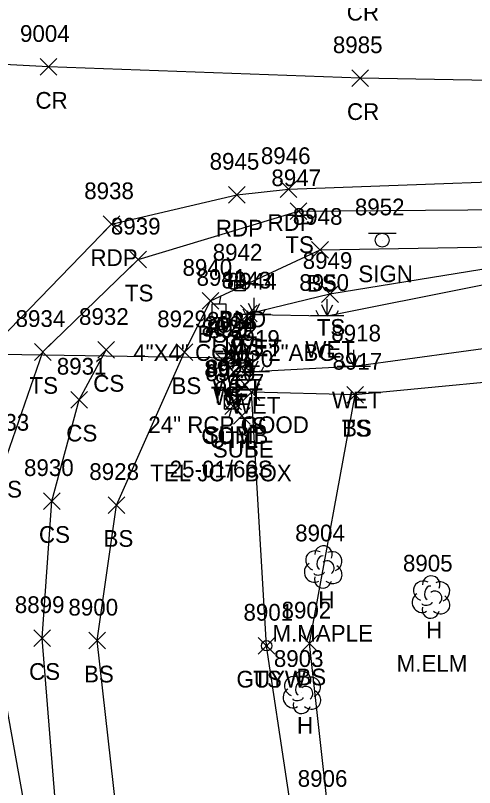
# Model space of a CAD drawing. Extents: x 1462089 to 1464015, y 730534 to 736144.
# Drawn here: x 1463265.1 to 1463320, y 734884.2 to 734976.7 of the extents above; entities that cross this region are included whole.
import ezdxf

# ---------------------------------------------------------------- set-up
doc = ezdxf.new("R2010")
doc.units = 0
for name, color, linetype in [('D_A', 7, 'Continuous'), ('D_C', 7, 'Continuous'), ('D_I', 7, 'Continuous'), ('D_TIC', 7, 'Continuous'), ('DCP', 7, 'Continuous'), ('L_A', 7, 'Continuous'), ('L_C', 7, 'Continuous'), ('L_I', 7, 'Continuous'), ('L_TIC', 7, 'Continuous'), ('LELB', 7, 'Continuous'), ('LTD', 7, 'Continuous'), ('LWET', 7, 'Continuous'), ('M_A', 7, 'Continuous'), ('M_C', 7, 'Continuous'), ('M_I', 7, 'Continuous'), ('MHBP', 7, 'Continuous'), ('P_A', 7, 'Continuous'), ('P_I', 7, 'Continuous'), ('P_TIC', 7, 'Continuous'), ('PET', 7, 'Continuous'), ('PRC', 7, 'Continuous'), ('S_A', 7, 'Continuous'), ('S_I', 7, 'Continuous'), ('SSGN', 7, 'Continuous'), ('U_A', 7, 'Continuous'), ('U_C', 7, 'Continuous'), ('U_I', 7, 'Continuous'), ('U_TIC', 7, 'Continuous'), ('UDEFAULT', 7, 'Continuous'), ('ULP', 7, 'Continuous'), ('UP', 7, 'Continuous'), ('UPGW', 7, 'Continuous')]:
    doc.layers.add(name, color=color, linetype=linetype)

msp = doc.modelspace()

# ---------------------------------------------------------------- linework, layer by layer
at = {"layer": 'D_TIC'}
for points in [[(1463290.042, 734934.667), (1463292.042, 734936.667)], [(1463292.042, 734934.667), (1463290.042, 734936.667)]]:
    msp.add_lwpolyline(points, dxfattribs=at)
at = {"layer": 'DCP'}
msp.add_lwpolyline([(1463180.1, 734937.44), (1463291.042, 734935.667)], dxfattribs=at)
at = {"layer": 'L_TIC'}
for points in [[(1463297.971, 734952.221), (1463299.971, 734954.221)], [(1463299.971, 734952.221), (1463297.971, 734954.221)], [(1463300.533, 734947.593), (1463302.533, 734949.593)], [(1463302.533, 734947.593), (1463300.533, 734949.593)], [(1463278.758, 734946.428), (1463280.758, 734948.428)], [(1463280.758, 734946.428), (1463278.758, 734948.428)], [(1463301.727, 734942.315), (1463303.727, 734944.315)], [(1463303.727, 734942.315), (1463301.727, 734944.315)], [(1463287.412, 734941.494), (1463289.412, 734943.494)], [(1463289.412, 734941.494), (1463287.412, 734943.494)], [(1463292.007, 734939.973), (1463294.007, 734941.973)], [(1463294.007, 734939.973), (1463292.007, 734941.973)], [(1463267.338, 734935.371), (1463269.338, 734937.371)], [(1463269.338, 734935.371), (1463267.338, 734937.371)], [(1463274.938, 734935.616), (1463276.938, 734937.616)], [(1463276.938, 734935.616), (1463274.938, 734937.616)], [(1463284.305, 734935.334), (1463286.305, 734937.334)], [(1463286.305, 734935.334), (1463284.305, 734937.334)], [(1463289.045, 734934.223), (1463291.045, 734936.223)], [(1463291.045, 734934.223), (1463289.045, 734936.223)], [(1463292.334, 734930.57), (1463294.334, 734932.57)], [(1463294.334, 734930.57), (1463292.334, 734932.57)], [(1463292.334, 734930.57), (1463294.334, 734932.57)], [(1463294.334, 734930.57), (1463292.334, 734932.57)], [(1463271.708, 734929.66), (1463273.708, 734931.66)], [(1463273.708, 734929.66), (1463271.708, 734931.66)], [(1463304.73, 734930.253), (1463306.73, 734932.253)], [(1463306.73, 734930.253), (1463304.73, 734932.253)], [(1463304.73, 734930.253), (1463306.73, 734932.253)], [(1463306.73, 734930.253), (1463304.73, 734932.253)], [(1463268.436, 734917.529), (1463270.436, 734919.529)], [(1463270.436, 734917.529), (1463268.436, 734919.529)], [(1463276.169, 734917.054), (1463278.169, 734919.054)], [(1463278.169, 734917.054), (1463276.169, 734919.054)], [(1463267.254, 734901.129), (1463269.254, 734903.129)], [(1463269.254, 734901.129), (1463267.254, 734903.129)], [(1463273.832, 734900.825), (1463275.832, 734902.825)], [(1463275.832, 734900.825), (1463273.832, 734902.825)], [(1463294.137, 734900.213), (1463296.137, 734902.213)], [(1463296.137, 734900.213), (1463294.137, 734902.213)], [(1463299.265, 734900.473), (1463301.265, 734902.473)], [(1463301.265, 734900.473), (1463299.265, 734902.473)]]:
    msp.add_lwpolyline(points, dxfattribs=at)
at = {"layer": 'LELB'}
for points in [[(1463264.438, 734721.407), (1463263.507, 734771.236), (1463263.833, 734824.888), (1463270.027, 734860.541), (1463262.385, 734902.806), (1463264.021, 734923.95), (1463268.338, 734936.371), (1463279.758, 734947.428), (1463298.971, 734953.221), (1463339.528, 734953.531), (1463370.453, 734953.761)], [(1463274.437, 734722.017), (1463275.239, 734770.638), (1463277.634, 734823.964), (1463279.43, 734861.116), (1463274.832, 734901.825), (1463277.169, 734918.054), (1463285.305, 734936.334), (1463288.412, 734942.494), (1463301.533, 734948.593), (1463339.117, 734949.223), (1463370.465, 734949.424)], [(1463341.575, 734817.643), (1463321.491, 734824.397), (1463302.22, 734837.233), (1463300.766, 734858.163), (1463300.153, 734867.868), (1463295.137, 734901.213), (1463293.334, 734931.57), (1463290.045, 734935.223), (1463293.007, 734940.973), (1463302.727, 734943.315), (1463339.117, 734949.223)], [(1463359.784, 734936.972), (1463331.585, 734933.717), (1463305.73, 734931.253), (1463293.334, 734931.57)], [(1463268.889, 734721.541), (1463269.274, 734771.054), (1463270.408, 734824.446), (1463271.473, 734862.411), (1463268.254, 734902.129), (1463269.436, 734918.529), (1463272.708, 734930.66), (1463275.938, 734936.616)], [(1463343.192, 734822.583), (1463325.193, 734831.999), (1463308.067, 734843.504), (1463305.277, 734856.307), (1463304.048, 734867.373), (1463300.265, 734901.473), (1463305.73, 734931.253)]]:
    msp.add_lwpolyline(points, dxfattribs=at)
at = {"layer": 'LTD'}
for p, q in [((1463301.894, 734910.707), (1463301.894, 734910.707)), ((1463301.894, 734910.707), (1463301.894, 734910.707)), ((1463314.798, 734907.093), (1463314.798, 734907.093)), ((1463314.798, 734907.093), (1463314.798, 734907.093)), ((1463299.344, 734895.677), (1463299.344, 734895.677)), ((1463299.344, 734895.677), (1463299.344, 734895.677))]:
    msp.add_line(p, q, dxfattribs=at)
for centre in [(1463301.941, 734912.141), (1463314.845, 734908.527), (1463299.391, 734897.111)]:
    msp.add_arc(centre, 1.047, 335.52715, 180.95627, dxfattribs=at)
for centre, major_axis, ratio, start_param, end_param in [((1463301.102, 734911.373), (1.21, -0.512), 0.895232, 1.570796, 4.712389), ((1463301.686, 734911.165), (-0.208, -0.792), 0.645439, 3.141593, 6.283185), ((1463302.936, 734911.29), (-1.141, -0.483), 0.949671, 1.570796, 4.712389), ((1463300.811, 734909.998), (0.584, -1.042), 0.959034, 3.141593, 6.283185), ((1463302.394, 734910.54), (-0.5, 0.667), 0.989748, 3.141593, 6.283185), ((1463302.894, 734909.873), (-1.09, 0.792), 0.841452, 1.570796, 4.712389), ((1463301.894, 734909.207), (0.265, 1.061), 0.942809, 1.570796, 4.712389), ((1463301.436, 734909.956), (-0.625, -0.083), 0.423636, 0, 3.141593), ((1463314.006, 734907.759), (1.21, -0.512), 0.895232, 1.570796, 4.712389), ((1463314.59, 734907.551), (-0.208, -0.792), 0.645439, 3.141593, 6.283185), ((1463315.84, 734907.676), (-1.141, -0.483), 0.949671, 1.570796, 4.712389), ((1463313.715, 734906.384), (0.584, -1.042), 0.959034, 3.141593, 6.283185), ((1463315.298, 734906.926), (-0.5, 0.667), 0.989748, 3.141593, 6.283185), ((1463314.34, 734906.343), (-0.625, -0.083), 0.423636, 0, 3.141593), ((1463315.798, 734906.26), (-1.09, 0.792), 0.841452, 1.570796, 4.712389), ((1463314.798, 734905.593), (0.265, 1.061), 0.942809, 1.570796, 4.712389), ((1463298.552, 734896.344), (1.21, -0.512), 0.895232, 1.570796, 4.712389), ((1463300.385, 734896.261), (-1.141, -0.483), 0.949671, 1.570796, 4.712389), ((1463299.135, 734896.136), (-0.208, -0.792), 0.645439, 3.141593, 6.283185), ((1463299.844, 734895.511), (-0.5, 0.667), 0.989748, 3.141593, 6.283185), ((1463298.261, 734894.969), (0.584, -1.042), 0.959034, 3.141593, 6.283185), ((1463300.344, 734894.844), (-1.09, 0.792), 0.841452, 1.570796, 4.712389), ((1463299.344, 734894.177), (0.265, 1.061), 0.942809, 1.570796, 4.712389), ((1463298.886, 734894.927), (-0.625, -0.083), 0.423636, 0, 3.141593)]:
    msp.add_ellipse(centre, major_axis=major_axis, ratio=ratio, start_param=start_param, end_param=end_param, dxfattribs=at)
at = {"layer": 'LWET'}
for p, q in [((1463293.653, 734940.839), (1463293.653, 734942.839)), ((1463302.401, 734940.682), (1463302.401, 734942.682)), ((1463293.653, 734940.839), (1463292.986, 734942.172)), ((1463293.653, 734940.839), (1463294.32, 734942.172)), ((1463302.401, 734940.682), (1463301.734, 734942.015)), ((1463302.401, 734940.682), (1463303.067, 734942.015)), ((1463295.653, 734940.839), (1463291.653, 734940.839)), ((1463292.653, 734940.839), (1463292.32, 734941.505)), ((1463294.653, 734940.839), (1463294.986, 734941.505)), ((1463304.401, 734940.682), (1463300.401, 734940.682)), ((1463301.401, 734940.682), (1463301.067, 734941.349)), ((1463303.401, 734940.682), (1463303.734, 734941.349)), ((1463291.266, 734936.156), (1463291.266, 734938.156)), ((1463291.266, 734936.156), (1463290.6, 734937.489)), ((1463291.266, 734936.156), (1463291.933, 734937.489)), ((1463291.38, 734935.016), (1463291.38, 734937.016)), ((1463293.266, 734936.156), (1463289.266, 734936.156)), ((1463290.266, 734936.156), (1463289.933, 734936.823)), ((1463291.38, 734935.016), (1463290.713, 734936.349)), ((1463291.38, 734935.016), (1463292.047, 734936.349)), ((1463292.266, 734936.156), (1463292.6, 734936.823)), ((1463293.47, 734933.987), (1463293.47, 734935.987)), ((1463305.577, 734934.638), (1463305.577, 734936.638)), ((1463290.38, 734935.016), (1463290.047, 734935.683)), ((1463292.38, 734935.016), (1463292.713, 734935.683)), ((1463293.47, 734933.987), (1463292.803, 734935.32)), ((1463293.47, 734933.987), (1463294.136, 734935.32)), ((1463304.577, 734934.638), (1463304.244, 734935.305)), ((1463305.577, 734934.638), (1463304.91, 734935.972)), ((1463305.577, 734934.638), (1463306.244, 734935.972)), ((1463306.577, 734934.638), (1463306.91, 734935.305)), ((1463293.38, 734935.016), (1463289.38, 734935.016)), ((1463292.47, 734933.987), (1463292.136, 734934.653)), ((1463294.47, 734933.987), (1463294.803, 734934.653)), ((1463307.577, 734934.638), (1463303.577, 734934.638)), ((1463295.47, 734933.987), (1463291.47, 734933.987))]:
    msp.add_line(p, q, dxfattribs=at)
msp.add_lwpolyline([(1463359.703, 734939.534), (1463331.295, 734938.128), (1463305.577, 734934.638), (1463293.47, 734933.987), (1463291.38, 734935.016), (1463291.266, 734936.156), (1463293.653, 734940.839), (1463302.401, 734940.682), (1463338.181, 734947.84), (1463369.972, 734946.235)], dxfattribs=at)
at = {"layer": 'MHBP'}
msp.add_lwpolyline([(1463291.32, 734944.929), (1463292.57, 734944.929), (1463292.57, 734943.679), (1463291.32, 734943.679)], close=True, dxfattribs=at)
msp.add_circle((1463291.945, 734944.304), 0.0833, dxfattribs=at)
at = {"layer": 'P_TIC'}
for points in [[(1463268.026, 734969.49), (1463270.026, 734971.49)], [(1463270.026, 734969.49), (1463268.026, 734971.49)], [(1463305.329, 734968.142), (1463307.329, 734970.142)], [(1463307.329, 734968.142), (1463305.329, 734970.142)], [(1463296.764, 734954.867), (1463298.764, 734956.867)], [(1463298.764, 734954.867), (1463296.764, 734956.867)], [(1463290.574, 734954.193), (1463292.574, 734956.193)], [(1463292.574, 734954.193), (1463290.574, 734956.193)], [(1463275.556, 734950.663), (1463277.556, 734952.663)], [(1463277.556, 734950.663), (1463275.556, 734952.663)]]:
    msp.add_lwpolyline(points, dxfattribs=at)
at = {"layer": 'PET'}
msp.add_lwpolyline([(1463257.855, 734929.751), (1463261.821, 734936.51), (1463276.556, 734951.663), (1463291.574, 734955.193), (1463297.764, 734955.867), (1463339.315, 734957.368), (1463370.338, 734956.311)], dxfattribs=at)
at = {"layer": 'PRC'}
msp.add_lwpolyline([(1463370.424, 734967.11), (1463339.737, 734968.555), (1463306.329, 734969.142), (1463269.026, 734970.49), (1463257.64, 734971.099)], dxfattribs=at)
at = {"layer": 'SSGN'}
for p, q in [((1463307.335, 734950.582), (1463310.668, 734950.582)), ((1463308.982, 734949.748), (1463308.982, 734949.748))]:
    msp.add_line(p, q, dxfattribs=at)
msp.add_circle((1463308.982, 734949.748), 0.833, dxfattribs=at)
at = {"layer": 'U_TIC'}
for points in [[(1463290.126, 734929.462), (1463292.126, 734931.462)], [(1463292.126, 734929.462), (1463290.126, 734931.462)], [(1463291.169, 734927.74), (1463293.169, 734929.74)], [(1463293.169, 734927.74), (1463291.169, 734929.74)]]:
    msp.add_lwpolyline(points, dxfattribs=at)
at = {"layer": 'UDEFAULT'}
for points in [[(1463290.138, 734928.89), (1463292.138, 734930.89)], [(1463292.138, 734928.89), (1463290.138, 734930.89)]]:
    msp.add_lwpolyline(points, dxfattribs=at)
at = {"layer": 'ULP'}
for p, q in [((1463289.608, 734942.963), (1463289.442, 734942.129)), ((1463288.608, 734940.463), (1463288.608, 734942.129)), ((1463288.608, 734942.129), (1463290.275, 734942.129)), ((1463290.275, 734942.129), (1463290.275, 734940.463)), ((1463289.442, 734941.296), (1463289.442, 734941.296)), ((1463290.275, 734940.463), (1463288.608, 734940.463)), ((1463289.192, 734939.629), (1463289.442, 734940.463))]:
    msp.add_line(p, q, dxfattribs=at)
at = {"layer": 'UP'}
for p, q in [((1463291.182, 734932.033), (1463290.932, 734931.2)), ((1463290.098, 734929.533), (1463290.098, 734931.2)), ((1463290.098, 734931.2), (1463291.765, 734931.2)), ((1463291.765, 734931.2), (1463291.765, 734929.533)), ((1463291.765, 734929.533), (1463290.098, 734929.533)), ((1463290.682, 734928.7), (1463290.932, 734929.533)), ((1463290.932, 734930.367), (1463290.932, 734930.367))]:
    msp.add_line(p, q, dxfattribs=at)
msp.add_circle((1463290.932, 734930.367), 0.833, dxfattribs=at)
at = {"layer": 'UPGW'}
for radius in [0.625, 0.0833]:
    msp.add_circle((1463295.137, 734901.213), radius, dxfattribs=at)

# ---------------------------------------------------------------- texts
at = {"layer": 'D_A'}
msp.add_text('P', height=2, dxfattribs=at).set_placement((1463290.42, 734930.667))
at = {"layer": 'D_C'}
msp.add_text('24" RCP GOOD', height=2, dxfattribs=at).set_placement((1463280.971, 734926.667))
at = {"layer": 'D_I'}
msp.add_text('2094', height=2, dxfattribs=at).set_placement((1463287.703, 734938.667))
at = {"layer": 'L_A'}
for s, p in [('TS', (1463297.38, 734948.221)), ('BS', (1463299.974, 734943.593)), ('TS', (1463278.167, 734942.428)), ('TS', (1463301.137, 734938.315)), ('BS', (1463286.853, 734937.494)), ('WET', (1463291.031, 734935.839)), ('TS', (1463291.417, 734935.973)), ('WET', (1463299.779, 734935.682)), ('TS', (1463266.747, 734931.371)), ('CS', (1463274.378, 734931.616)), ('BS', (1463283.746, 734931.334)), ('WET', (1463288.644, 734931.156)), ('TS', (1463288.455, 734930.223)), ('WET', (1463288.758, 734930.016)), ('WET', (1463302.955, 734929.638)), ('WET', (1463290.848, 734928.987)), ('TS', (1463291.744, 734926.57)), ('TS', (1463291.744, 734926.57)), ('CS', (1463271.149, 734925.66)), ('TS', (1463304.14, 734926.253)), ('BS', (1463304.171, 734926.253)), ('TS', (1463262.43, 734918.95)), ('CS', (1463267.877, 734913.529)), ('BS', (1463275.61, 734913.054)), ('H', (1463301.327, 734905.707)), ('H', (1463314.231, 734902.093)), ('CS', (1463266.695, 734897.129)), ('BS', (1463273.273, 734896.825)), ('TS', (1463293.547, 734896.213)), ('BS', (1463298.706, 734896.473)), ('H', (1463298.777, 734890.677))]:
    msp.add_text(s, height=2, dxfattribs=at).set_placement(p)
at = {"layer": 'L_C'}
for s, p in [('M.MAPLE', (1463295.831, 734901.707)), ('M.ELM', (1463310.704, 734898.093))]:
    msp.add_text(s, height=2, dxfattribs=at).set_placement(p)
at = {"layer": 'L_I'}
for s, p in [('8947', (1463295.711, 734956.221)), ('8948', (1463298.274, 734951.593)), ('8939', (1463276.49, 734950.428)), ('8949', (1463299.46, 734946.315)), ('8940', (1463285.066, 734945.494)), ('8943', (1463289.748, 734943.973)), ('8944', (1463290.393, 734943.839)), ('8950', (1463299.054, 734943.682)), ('8932', (1463272.678, 734939.616)), ('8934', (1463265.078, 734939.371)), ('8929', (1463282.037, 734939.334)), ('8923', (1463288.007, 734939.156)), ('8921', (1463287.353, 734938.223)), ('8922', (1463288.12, 734938.016)), ('8919', (1463290.769, 734936.987)), ('8918', (1463302.884, 734937.638)), ('8920', (1463289.988, 734934.57)), ('8920', (1463289.988, 734934.57)), ('8917', (1463303.037, 734934.253)), ('8917', (1463303.037, 734934.253)), ('8931', (1463270.015, 734933.66)), ('8933', (1463260.761, 734926.95)), ('8930', (1463266.09, 734921.529)), ('8928', (1463273.909, 734921.054)), ('8904', (1463298.556, 734913.707)), ('8905', (1463311.46, 734910.093)), ('8899', (1463264.987, 734905.129)), ('8900', (1463271.407, 734904.825)), ('8902', (1463296.927, 734904.473)), ('8901', (1463292.366, 734904.213)), ('8903', (1463296.005, 734898.677)), ('8906', (1463298.864, 734884.331))]:
    msp.add_text(s, height=2, dxfattribs=at).set_placement(p)
at = {"layer": 'M_A'}
msp.add_text('BND', height=2, dxfattribs=at).set_placement((1463289.433, 734939.304))
at = {"layer": 'M_C'}
msp.add_text('4"X4" CONC-2"ABG', height=2, dxfattribs=at).set_placement((1463279.166, 734935.304))
at = {"layer": 'M_I'}
msp.add_text('8942', height=2, dxfattribs=at).set_placement((1463288.685, 734947.304))
at = {"layer": 'P_A'}
for s, p in [('CR', (1463304.739, 734976.039)), ('CR', (1463267.459, 734965.49)), ('CR', (1463304.762, 734964.142)), ('RDP', (1463295.252, 734950.867)), ('RDP', (1463289.062, 734950.193)), ('RDP', (1463274.044, 734946.663))]:
    msp.add_text(s, height=2, dxfattribs=at).set_placement(p)
at = {"layer": 'P_I'}
for s, p in [('9004', (1463265.609, 734973.49)), ('8985', (1463303.069, 734972.142)), ('8945', (1463288.314, 734958.193)), ('8946', (1463294.449, 734958.867)), ('8938', (1463273.296, 734954.663))]:
    msp.add_text(s, height=2, dxfattribs=at).set_placement(p)
at = {"layer": 'S_A'}
msp.add_text('SIGN', height=2, dxfattribs=at).set_placement((1463306.12, 734944.728))
at = {"layer": 'S_I'}
msp.add_text('8952', height=2, dxfattribs=at).set_placement((1463305.703, 734952.728))
at = {"layer": 'U_A'}
for s, p in [('LI', (1463288.544, 734936.296)), ('COMB', (1463287.317, 734925.367)), ('SUBT', (1463287.622, 734925.462)), ('UTIL', (1463288.303, 734924.89)), ('SUBE', (1463288.704, 734923.74)), ('GUYW', (1463291.531, 734896.213))]:
    msp.add_text(s, height=2, dxfattribs=at).set_placement(p)
at = {"layer": 'U_C'}
for s, p in [('25-01/66S', (1463283.53, 734921.367)), ('TEL JCT BOX', (1463281.201, 734920.89))]:
    msp.add_text(s, height=2, dxfattribs=at).set_placement(p)
at = {"layer": 'U_I'}
for s, p in [('8941', (1463286.749, 734944.296)), ('8924', (1463287.672, 734933.367)), ('8925', (1463287.866, 734933.462)), ('8926', (1463287.823, 734932.89)), ('8927', (1463288.909, 734931.74)), ('8901', (1463292.366, 734904.213))]:
    msp.add_text(s, height=2, dxfattribs=at).set_placement(p)

doc.saveas('drawing.dxf')
